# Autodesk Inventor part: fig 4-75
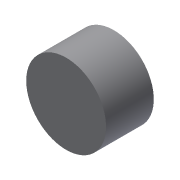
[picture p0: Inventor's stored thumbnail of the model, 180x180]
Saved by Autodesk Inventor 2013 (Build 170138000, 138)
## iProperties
Created: 2012-07
Part Number: fig 4-75
Material: Generic
Document SubType Name: Modeling
Designer: CADCIM
Density: 1 g/cm^3
Author: CADCIM
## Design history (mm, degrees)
sketch "Sketch1"
  geometry: C1 r 8.37 at (0, 0)
  constraints: 1 centre point
  dimensions: "d0" = 10 dimension on C1.centre C1
extrude "Extrusion1" new body sketch "Sketch1" distance "d0" = 10; taper "d1" = 0 deg
body "Solid1"
